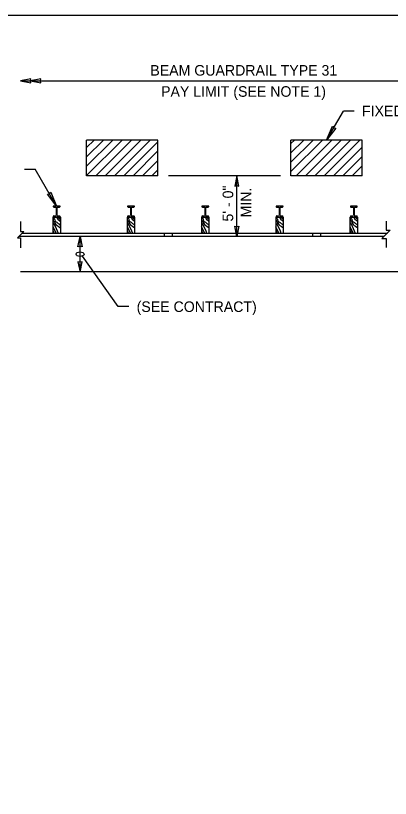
# Model space of a CAD drawing. Extents: x 99862 to 103680, y 99470 to 102076.
# Drawn here: x 101437 to 102004, y 100890 to 102076 of the extents above; entities that cross this region are included whole.
import ezdxf

# ---------------------------------------------------------------- set-up
doc = ezdxf.new("R2010")
doc.units = 0
for name, color, linetype in [('Level 1', 7, 'Continuous'), ('Level 10', 7, 'Continuous'), ('Level 11', 7, 'Continuous'), ('Level 13', 7, 'Continuous'), ('Level 15', 7, 'Continuous'), ('Level 17', 7, 'Continuous'), ('Level 20', 7, 'Continuous'), ('Level 21', 7, 'Continuous'), ('Level 9', 7, 'Continuous')]:
    doc.layers.add(name, color=color, linetype=linetype)

msp = doc.modelspace()

# ---------------------------------------------------------------- linework, layer by layer
at = {"layer": 'Level 1'}
for p, q in [((101441.4, 101741.5), (101994.4, 101741.5)), ((101446.4, 101746.4), (101999.4, 101746.4))]:
    msp.add_line(p, q, dxfattribs=at)
msp.add_lwpolyline([(99862, 99999.5), (103151, 99999.5), (103151, 102075.5), (99862, 102075.5)], close=True, dxfattribs=at)
at = {"layer": 'Level 10'}
for p, q in [((101492.7, 101770.4), (101504.7, 101770.4)), ((101492.7, 101770.4), (101492.7, 101746.4)), ((101504.7, 101746.4), (101504.7, 101770.4)), ((101605.2, 101770.4), (101617.2, 101770.4)), ((101605.2, 101770.4), (101605.2, 101746.4)), ((101617.2, 101746.4), (101617.2, 101770.4)), ((101717.7, 101770.4), (101729.7, 101770.4)), ((101717.7, 101770.4), (101717.7, 101746.4)), ((101729.7, 101746.4), (101729.7, 101770.4)), ((101830.2, 101770.4), (101842.2, 101770.4)), ((101830.2, 101770.4), (101830.2, 101746.4)), ((101842.2, 101746.4), (101842.2, 101770.4)), ((101942.7, 101770.4), (101954.7, 101770.4)), ((101942.7, 101770.4), (101942.7, 101746.4)), ((101954.7, 101746.4), (101954.7, 101770.4)), ((101492.7, 101746.4), (101504.7, 101746.4)), ((101497.8, 101746.4), (101497.8, 101746.4)), ((101497.8, 101746.4), (101497.8, 101746.4)), ((101499.7, 101746.4), (101499.7, 101746.4)), ((101499.7, 101746.4), (101499.7, 101746.4)), ((101605.2, 101746.4), (101617.2, 101746.4)), ((101610.3, 101746.4), (101610.3, 101746.4)), ((101610.3, 101746.4), (101610.3, 101746.4)), ((101612.2, 101746.4), (101612.2, 101746.4)), ((101612.2, 101746.4), (101612.2, 101746.4)), ((101717.7, 101746.4), (101729.7, 101746.4)), ((101722.8, 101746.4), (101722.8, 101746.4)), ((101722.8, 101746.4), (101722.8, 101746.4)), ((101724.7, 101746.4), (101724.7, 101746.4)), ((101724.7, 101746.4), (101724.7, 101746.4)), ((101830.2, 101746.4), (101842.2, 101746.4)), ((101835.3, 101746.4), (101835.3, 101746.4)), ((101835.3, 101746.4), (101835.3, 101746.4)), ((101837.2, 101746.4), (101837.2, 101746.4)), ((101837.2, 101746.4), (101837.2, 101746.4)), ((101942.7, 101746.4), (101954.7, 101746.4)), ((101947.8, 101746.4), (101947.8, 101746.4)), ((101947.8, 101746.4), (101947.8, 101746.4)), ((101949.7, 101746.4), (101949.7, 101746.4)), ((101949.7, 101746.4), (101949.7, 101746.4))]:
    msp.add_line(p, q, dxfattribs=at)
at = {"layer": 'Level 11'}
for p, q in [((101661.2, 101746.3), (101661.2, 101741.3)), ((101673.5, 101746.8), (101673.5, 101741.7)), ((101885.8, 101746.3), (101885.8, 101741.3)), ((101898.2, 101746.4), (101898.2, 101741.5))]:
    msp.add_line(p, q, dxfattribs=at)
at = {"layer": 'Level 13'}
for p, q in [((101492.6, 101756.5), (101497.2, 101746.5)), ((101605.1, 101756.5), (101609.7, 101746.5)), ((101717.6, 101756.5), (101722.2, 101746.5)), ((101830.1, 101756.5), (101834.7, 101746.5)), ((101942.6, 101756.5), (101947.2, 101746.5))]:
    msp.add_line(p, q, dxfattribs=at)
for points in [[(101492.7, 101768.2), (101494.8, 101764), (101495.2, 101763.6), (101495.6, 101762.2), (101497.5, 101759.5), (101504.7, 101753.9)], [(101493.1, 101762.3), (101494.3, 101760.3), (101500.7, 101746.4)], [(101493.5, 101770.4), (101494.7, 101768.2), (101495.2, 101767.8), (101495.6, 101766.4), (101497.7, 101763.3), (101499.6, 101762.2), (101500, 101761.7), (101502.1, 101760.3), (101502.3, 101760.1), (101504.7, 101757.8)], [(101498.4, 101770.4), (101499.3, 101769.1), (101499.7, 101768.9), (101499.8, 101768.2), (101501.1, 101766.4), (101502.3, 101765.8), (101502.6, 101765.3), (101504.7, 101763.9)], [(101501.1, 101770.5), (101501.6, 101769.8), (101502.5, 101768.5), (101503.4, 101767.9), (101504.6, 101767.1)], [(101502.6, 101770.4), (101502.9, 101769.1), (101504.6, 101768)], [(101605.2, 101768.2), (101607.3, 101764), (101607.7, 101763.6), (101608.1, 101762.2), (101610, 101759.5), (101617.2, 101753.9)], [(101605.6, 101762.3), (101606.8, 101760.3), (101613.2, 101746.4)], [(101606, 101770.4), (101607.2, 101768.2), (101607.7, 101767.8), (101608.1, 101766.4), (101610.2, 101763.3), (101612.1, 101762.2), (101612.5, 101761.7), (101614.6, 101760.3), (101614.8, 101760.1), (101617.2, 101757.8)], [(101610.9, 101770.4), (101611.8, 101769.1), (101612.2, 101768.9), (101612.3, 101768.2), (101613.6, 101766.4), (101614.8, 101765.8), (101615.1, 101765.3), (101617.2, 101763.9)], [(101613.6, 101770.5), (101614.1, 101769.8), (101615, 101768.5), (101615.9, 101767.9), (101617.1, 101767.1)], [(101615.1, 101770.4), (101615.4, 101769.1), (101617.1, 101768)], [(101717.7, 101768.2), (101719.8, 101764), (101720.2, 101763.6), (101720.6, 101762.2), (101722.5, 101759.5), (101729.7, 101753.9)], [(101718.1, 101762.3), (101719.3, 101760.3), (101725.7, 101746.4)], [(101718.5, 101770.4), (101719.7, 101768.2), (101720.2, 101767.8), (101720.6, 101766.4), (101722.7, 101763.3), (101724.6, 101762.2), (101725, 101761.7), (101727.1, 101760.3), (101727.3, 101760.1), (101729.7, 101757.8)], [(101723.4, 101770.4), (101724.3, 101769.1), (101724.7, 101768.9), (101724.8, 101768.2), (101726.1, 101766.4), (101727.3, 101765.8), (101727.6, 101765.3), (101729.7, 101763.9)], [(101726.1, 101770.5), (101726.6, 101769.8), (101727.5, 101768.5), (101728.4, 101767.9), (101729.6, 101767.1)], [(101727.6, 101770.4), (101727.9, 101769.1), (101729.6, 101768)], [(101830.2, 101768.2), (101832.3, 101764), (101832.7, 101763.6), (101833.1, 101762.2), (101835, 101759.5), (101842.2, 101753.9)], [(101830.6, 101762.3), (101831.8, 101760.3), (101838.2, 101746.4)], [(101831, 101770.4), (101832.2, 101768.2), (101832.7, 101767.8), (101833.1, 101766.4), (101835.2, 101763.3), (101837.1, 101762.2), (101837.5, 101761.7), (101839.6, 101760.3), (101839.8, 101760.1), (101842.2, 101757.8)], [(101835.9, 101770.4), (101836.8, 101769.1), (101837.2, 101768.9), (101837.3, 101768.2), (101838.6, 101766.4), (101839.8, 101765.8), (101840.1, 101765.3), (101842.2, 101763.9)], [(101838.6, 101770.5), (101839.1, 101769.8), (101840, 101768.5), (101840.9, 101767.9), (101842.1, 101767.1)], [(101840.1, 101770.4), (101840.4, 101769.1), (101842.1, 101768)], [(101942.7, 101768.2), (101944.8, 101764), (101945.2, 101763.6), (101945.6, 101762.2), (101947.5, 101759.5), (101954.7, 101753.9)], [(101943.1, 101762.3), (101944.3, 101760.3), (101950.7, 101746.4)], [(101943.5, 101770.4), (101944.7, 101768.2), (101945.2, 101767.8), (101945.6, 101766.4), (101947.7, 101763.3), (101949.6, 101762.2), (101950, 101761.7), (101952.1, 101760.3), (101952.3, 101760.1), (101954.7, 101757.8)], [(101948.4, 101770.4), (101949.3, 101769.1), (101949.7, 101768.9), (101949.8, 101768.2), (101951.1, 101766.4), (101952.3, 101765.8), (101952.6, 101765.3), (101954.7, 101763.9)], [(101951.1, 101770.5), (101951.6, 101769.8), (101952.5, 101768.5), (101953.4, 101767.9), (101954.6, 101767.1)], [(101952.6, 101770.4), (101952.9, 101769.1), (101954.6, 101768)], [(101492.7, 101750.6), (101492.8, 101750.3), (101493, 101750.1), (101493.3, 101749.5), (101493.8, 101748.4), (101494.2, 101747.3), (101494.4, 101746.7), (101494.7, 101746.2)], [(101605.2, 101750.6), (101605.3, 101750.3), (101605.5, 101750.1), (101605.8, 101749.5), (101606.3, 101748.4), (101606.7, 101747.3), (101606.9, 101746.7), (101607.2, 101746.2)], [(101717.7, 101750.6), (101717.8, 101750.3), (101718, 101750.1), (101718.3, 101749.5), (101718.8, 101748.4), (101719.2, 101747.3), (101719.4, 101746.7), (101719.7, 101746.2)], [(101830.2, 101750.6), (101830.3, 101750.3), (101830.5, 101750.1), (101830.8, 101749.5), (101831.3, 101748.4), (101831.7, 101747.3), (101831.9, 101746.7), (101832.2, 101746.2)], [(101942.7, 101750.6), (101942.8, 101750.3), (101943, 101750.1), (101943.3, 101749.5), (101943.8, 101748.4), (101944.2, 101747.3), (101944.4, 101746.7), (101944.7, 101746.2)]]:
    msp.add_spline(points, degree=3, dxfattribs=at)
at = {"layer": 'Level 15'}
for p, q in [((101443.9, 101976.7), (102122.5, 101976.7)), ((101907.3, 101887.1), (101932.8, 101931.1)), ((101948.9, 101931.1), (101932.9, 101931.1)), ((101450.1, 101843.2), (101466.1, 101843.2)), ((101498.6, 101786.9), (101466.1, 101843.2)), ((101837.3, 101833.1), (101668, 101833.1)), ((101771.5, 101741.5), (101771.5, 101827.7)), ((101534, 101687.3), (101534, 101741.3)), ((101591.7, 101634.9), (101537.7, 101711.5)), ((101607.7, 101634.9), (101591.7, 101634.9))]:
    msp.add_line(p, q, dxfattribs=at)
for points in [[(101443.9, 101976.7), (101459.6, 101973.6), (101458.9, 101976.7), (101459.6, 101979.8)], [(101458.9, 101976.7), (101474.6, 101973.6), (101473.9, 101976.7), (101474.6, 101979.8)], [(101907.3, 101887.1), (101916.2, 101908.3), (101918.2, 101905.9), (101921.3, 101905.4)], [(101498.6, 101786.9), (101484.6, 101805.2), (101487.7, 101805.7), (101489.8, 101808.1)], [(101771.5, 101741.3), (101768.4, 101757), (101771.5, 101756.3), (101774.6, 101757)], [(101534, 101741.3), (101537.1, 101725.6), (101534, 101726.3), (101530.9, 101725.6)], [(101534, 101687.3), (101537.1, 101703), (101534, 101702.3), (101530.9, 101703)]]:
    msp.add_lwpolyline(points, close=True, dxfattribs=at)
for points in [[(101443.9, 101763.7), (101443.9, 101748.8), (101448.7, 101748.8), (101439.1, 101739.1), (101443.9, 101739.1), (101443.9, 101724.2)], [(101997.4, 101764.2), (101997.4, 101750.9), (102003.8, 101750.9), (101990.9, 101738), (101997.4, 101738), (101997.4, 101724.6)]]:
    msp.add_lwpolyline(points, dxfattribs=at)
msp.add_ellipse((101534, 101714.3), major_axis=(-6, 0.02), ratio=0.57735, dxfattribs=at)
at = {"layer": 'Level 17'}
for p, q in [((101544, 101833.1), (101544, 101887.1)), ((101652, 101887.1), (101544, 101887.1)), ((101544, 101875.7), (101555.4, 101887.1)), ((101544, 101861.6), (101569.6, 101887.1)), ((101544, 101847.4), (101583.7, 101887.1)), ((101544, 101833.3), (101597.8, 101887.1)), ((101558, 101833.1), (101612, 101887.1)), ((101572.1, 101833.1), (101626.1, 101887.1)), ((101586.3, 101833.1), (101640.3, 101887.1)), ((101600.4, 101833.1), (101652, 101884.7)), ((101652, 101833.1), (101652, 101887.1)), ((101961.3, 101887.1), (101853.3, 101887.1)), ((101853.3, 101833.1), (101853.3, 101887.1)), ((101853.3, 101881.7), (101858.7, 101887.1)), ((101853.3, 101867.6), (101872.8, 101887.1)), ((101853.3, 101853.5), (101886.9, 101887.1)), ((101853.3, 101839.3), (101901.1, 101887.1)), ((101861.2, 101833.1), (101915.2, 101887.1)), ((101875.4, 101833.1), (101929.4, 101887.1)), ((101889.5, 101833.1), (101943.5, 101887.1)), ((101903.6, 101833.1), (101957.6, 101887.1)), ((101961.3, 101833.1), (101961.3, 101887.1)), ((101614.5, 101833.1), (101652, 101870.6)), ((101917.8, 101833.1), (101961.3, 101876.6)), ((101628.7, 101833.1), (101652, 101856.4)), ((101931.9, 101833.1), (101961.3, 101862.5)), ((101642.8, 101833.1), (101652, 101842.3)), ((101946.1, 101833.1), (101961.3, 101848.3)), ((101652, 101833.1), (101544, 101833.1)), ((101961.3, 101833.1), (101853.3, 101833.1)), ((101960.2, 101833.1), (101961.3, 101834.2))]:
    msp.add_line(p, q, dxfattribs=at)
at = {"layer": 'Level 20'}
msp.add_lwpolyline([(101771.4, 101833.1), (101768.3, 101817.4), (101771.4, 101818.1), (101774.5, 101817.4)], close=True, dxfattribs=at)
at = {"layer": 'Level 21'}
msp.add_line((102995.3, 101687.5), (101443.9, 101687.5), dxfattribs=at)
at = {"layer": 'Level 9'}
for p, q in [((101497.8, 101785), (101497.8, 101778.9)), ((101499.4, 101778.9), (101499.4, 101785)), ((101610.3, 101785), (101610.3, 101778.9)), ((101611.9, 101778.9), (101611.9, 101785)), ((101722.8, 101785), (101722.8, 101778.9)), ((101724.4, 101778.9), (101724.4, 101785)), ((101835.3, 101785), (101835.3, 101778.9)), ((101836.9, 101778.9), (101836.9, 101785)), ((101947.8, 101785), (101947.8, 101778.9)), ((101949.4, 101778.9), (101949.4, 101785)), ((101497.8, 101778.9), (101497.8, 101772.7)), ((101499.3, 101772.7), (101499.4, 101778.9)), ((101610.3, 101778.9), (101610.3, 101772.7)), ((101611.8, 101772.7), (101611.9, 101778.9)), ((101722.8, 101778.9), (101722.8, 101772.7)), ((101724.3, 101772.7), (101724.4, 101778.9)), ((101835.3, 101778.9), (101835.3, 101772.7)), ((101836.8, 101772.7), (101836.9, 101778.9)), ((101947.8, 101778.9), (101947.8, 101772.7)), ((101949.3, 101772.7), (101949.4, 101778.9))]:
    msp.add_line(p, q, dxfattribs=at)
for points in [[(101498.6, 101786.9), (101493.4, 101786.9), (101493.4, 101786.4)], [(101494.2, 101785.6), (101497.2, 101785.6)], [(101503.8, 101786.4), (101503.8, 101786.9), (101498.6, 101786.9)], [(101500, 101785.6), (101503, 101785.6)], [(101611.1, 101786.9), (101605.9, 101786.9), (101605.9, 101786.4)], [(101606.7, 101785.6), (101609.7, 101785.6)], [(101616.3, 101786.4), (101616.3, 101786.9), (101611.1, 101786.9)], [(101612.5, 101785.6), (101615.5, 101785.6)], [(101723.6, 101786.9), (101718.4, 101786.9), (101718.4, 101786.4)], [(101719.2, 101785.6), (101722.2, 101785.6)], [(101728.8, 101786.4), (101728.8, 101786.9), (101723.6, 101786.9)], [(101725, 101785.6), (101728, 101785.6)], [(101836.1, 101786.9), (101830.9, 101786.9), (101830.9, 101786.4)], [(101831.7, 101785.6), (101834.7, 101785.6)], [(101841.3, 101786.4), (101841.3, 101786.9), (101836.1, 101786.9)], [(101837.5, 101785.6), (101840.5, 101785.6)], [(101948.6, 101786.9), (101943.4, 101786.9), (101943.4, 101786.4)], [(101944.2, 101785.6), (101947.2, 101785.6)], [(101953.8, 101786.4), (101953.8, 101786.9), (101948.6, 101786.9)], [(101950, 101785.6), (101953, 101785.6)], [(101493.4, 101771.4), (101493.4, 101770.9), (101498.6, 101770.9)], [(101497.2, 101772.1), (101494.2, 101772.2)], [(101498.6, 101770.9), (101503.7, 101770.9), (101503.7, 101771.4)], [(101503, 101772.1), (101499.9, 101772.1)], [(101605.9, 101771.4), (101605.9, 101770.9), (101611.1, 101770.9)], [(101609.7, 101772.1), (101606.7, 101772.2)], [(101611.1, 101770.9), (101616.2, 101770.9), (101616.2, 101771.4)], [(101615.5, 101772.1), (101612.4, 101772.1)], [(101718.4, 101771.4), (101718.4, 101770.9), (101723.6, 101770.9)], [(101722.2, 101772.1), (101719.2, 101772.2)], [(101723.6, 101770.9), (101728.7, 101770.9), (101728.7, 101771.4)], [(101728, 101772.1), (101724.9, 101772.1)], [(101830.9, 101771.4), (101830.9, 101770.9), (101836.1, 101770.9)], [(101834.7, 101772.1), (101831.7, 101772.2)], [(101836.1, 101770.9), (101841.2, 101770.9), (101841.2, 101771.4)], [(101840.5, 101772.1), (101837.4, 101772.1)], [(101943.4, 101771.4), (101943.4, 101770.9), (101948.6, 101770.9)], [(101947.2, 101772.1), (101944.2, 101772.2)], [(101948.6, 101770.9), (101953.7, 101770.9), (101953.7, 101771.4)], [(101953, 101772.1), (101949.9, 101772.1)]]:
    msp.add_lwpolyline(points, dxfattribs=at)
for centre, radius, start, end in [((101494.2, 101786.4), 0.788, 179.9273, 269.9273), ((101497.2, 101785), 0.591, 359.9273, 89.9273), ((101500, 101785), 0.591, 89.9273, 179.9273), ((101503, 101786.4), 0.788, 269.9273, 359.9273), ((101606.7, 101786.4), 0.788, 179.9273, 269.9273), ((101609.7, 101785), 0.591, 359.9273, 89.9273), ((101612.5, 101785), 0.591, 89.9273, 179.9273), ((101615.5, 101786.4), 0.788, 269.9273, 359.9273), ((101719.2, 101786.4), 0.788, 179.9273, 269.9273), ((101722.2, 101785), 0.591, 359.9273, 89.9273), ((101725, 101785), 0.591, 89.9273, 179.9273), ((101728, 101786.4), 0.788, 269.9273, 359.9273), ((101831.7, 101786.4), 0.788, 179.9273, 269.9273), ((101834.7, 101785), 0.591, 359.9273, 89.9273), ((101837.5, 101785), 0.591, 89.9273, 179.9273), ((101840.5, 101786.4), 0.788, 269.9273, 359.9273), ((101944.2, 101786.4), 0.788, 179.9273, 269.9273), ((101947.2, 101785), 0.591, 359.9273, 89.9273), ((101950, 101785), 0.591, 89.9273, 179.9273), ((101953, 101786.4), 0.788, 269.9273, 359.9273), ((101494.2, 101771.4), 0.788, 89.9273, 179.9478), ((101499.9, 101772.7), 0.591, 179.9273, 269.9273), ((101503, 101771.4), 0.788, 359.9478, 89.9273), ((101606.7, 101771.4), 0.788, 89.9273, 179.9478), ((101612.4, 101772.7), 0.591, 179.9273, 269.9273), ((101615.5, 101771.4), 0.788, 359.9478, 89.9273), ((101719.2, 101771.4), 0.788, 89.9273, 179.9478), ((101724.9, 101772.7), 0.591, 179.9273, 269.9273), ((101728, 101771.4), 0.788, 359.9478, 89.9273), ((101831.7, 101771.4), 0.788, 89.9273, 179.9478), ((101837.4, 101772.7), 0.591, 179.9273, 269.9273), ((101840.5, 101771.4), 0.788, 359.9478, 89.9273), ((101944.2, 101771.4), 0.788, 89.9273, 179.9478), ((101949.9, 101772.7), 0.591, 179.9273, 269.9273), ((101953, 101771.4), 0.788, 359.9478, 89.9273)]:
    msp.add_arc(centre, radius, start, end, dxfattribs=at)

# ---------------------------------------------------------------- texts
at = {"layer": 'Level 15'}
for s, p in [('5\' - 0" ', (101765.9, 101763.8)), ('MIN.', (101793.1, 101770))]:
    msp.add_text(s, height=16, rotation=90, dxfattribs=at).set_placement(p)
at = {"layer": 'Level 20'}
for s, p in [('BEAM GUARDRAIL TYPE 31 ', (101640.4, 101984.7)), ('PAY LIMIT (SEE NOTE 1)', (101656.7, 101952.7)), ('(SEE CONTRACT)', (101619.7, 101626.9))]:
    msp.add_text(s, height=16, dxfattribs=at).set_placement(p)
msp.add_text('FIXED FEATURE (TYP.)', height=16, rotation=360, dxfattribs=at).set_placement((101960.9, 101923.1))

doc.saveas('drawing.dxf')
